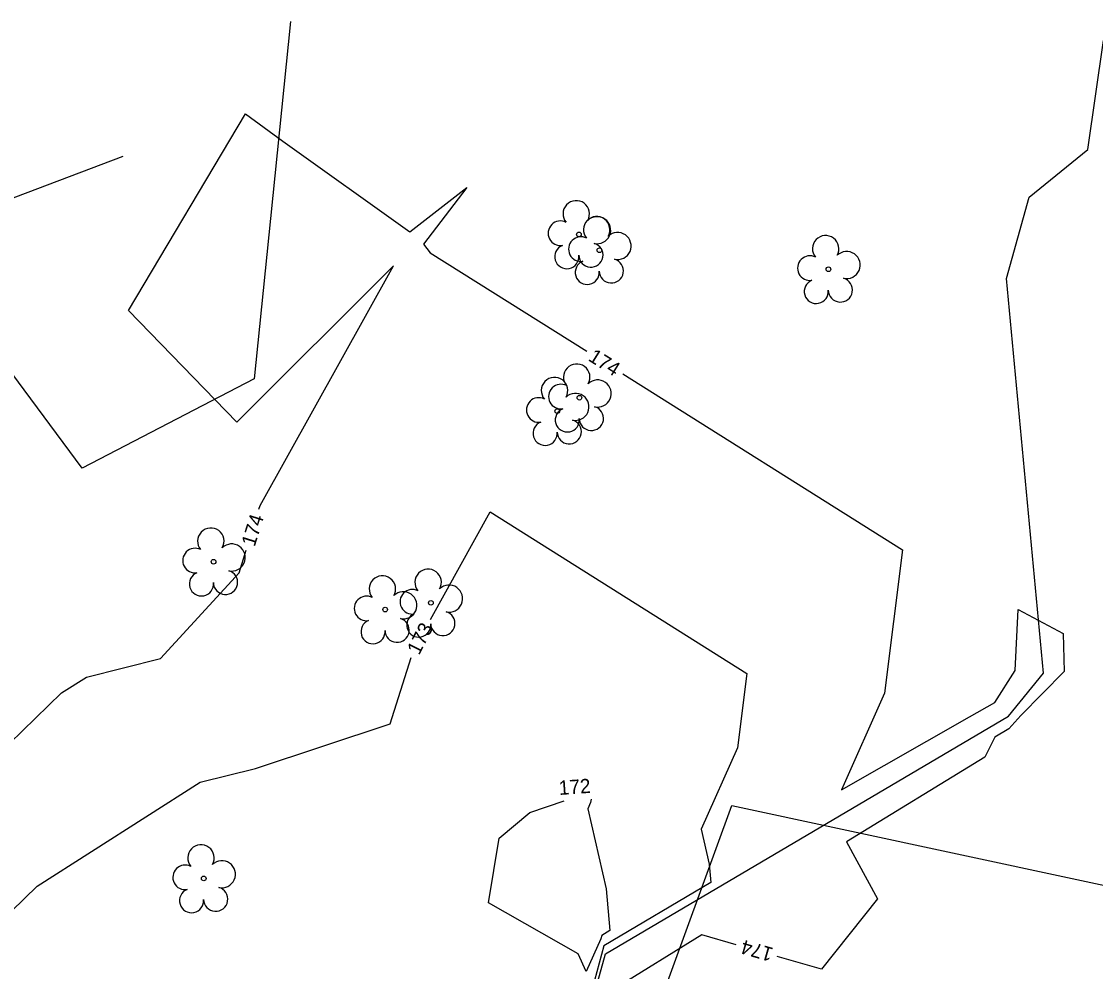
# Model space of a CAD drawing. Extents: x 2086416 to 2115205, y 575507 to 632762.
# Drawn here: x 2112356.1 to 2112506.7, y 581838.5 to 581971.8 of the extents above; entities that cross this region are included whole.
import ezdxf

# ---------------------------------------------------------------- set-up
doc = ezdxf.new("R2010")
doc.units = 0
for name, color, linetype in [('DTM Contours Minor', 7, 'Continuous'), ('DTM Contours Minor Text', 7, 'Continuous'), ('Exist Hydro Stream or Body of Water', 7, 'Continuous'), ('Exist Vegetation Tree CELL', 7, 'Continuous'), ('Exist Vegetation Woods Line', 7, 'Continuous')]:
    doc.layers.add(name, color=color, linetype=linetype)

# ---------------------------------------------------------------- blocks, each defined once
blk = doc.blocks.new('EXIST VEGETATION TREE')
at = {"layer": 'Exist Vegetation Tree CELL'}
blk.add_line((0, 0), (0, 0), dxfattribs=at)
blk.add_circle((0, 0), 0.00652, dxfattribs=at)
for centre, radius, start, end in [((-0.0077, 0.0575), 0.0371, 330.1651, 219.7134), ((-0.0521, 0.0031), 0.0345, 62.6636, 279.3457), ((0.051, 0.0118), 0.038, 257.1011, 134.1999), ((0.0335, -0.058), 0.034, 181.2822, 74.56), ((-0.0341, -0.0624), 0.0338, 111.5671, 6.231)]:
    blk.add_arc(centre, radius, start, end, dxfattribs=at)

msp = doc.modelspace()

# ---------------------------------------------------------------- linework, layer by layer
at = {"layer": 'DTM Contours Minor'}
for points in [[(2112389.4, 581903.35), (2112389.57, 581903.86), (2112408.27, 581937.5), (2112386.3, 581915.55), (2112371.1, 581931.24), (2112387.5, 581958.79), (2112392.75, 581954.99), (2112410.55, 581942.25), (2112418.57, 581948.48), (2112412.46, 581940.54), (2112413.43, 581939.32), (2112435.37, 581925.52)], [(2112315.08, 581919.53), (2112313.29, 581930.07), (2112313.19, 581931.24), (2112370.35, 581952.85)], [(2112440.45, 581922.33), (2112479.65, 581897.67), (2112477.15, 581877.58), (2112471.1, 581864.01), (2112489.03, 581874.23), (2112492.6, 581876.27), (2112495.44, 581880.72), (2112495.89, 581889.28), (2112502.17, 581885.91), (2112502.32, 581880.59), (2112496.23, 581874.43), (2112494.55, 581872.58), (2112492.59, 581871.4), (2112491.2, 581868.61), (2112471.79, 581856.7), (2112476.16, 581848.74), (2112468.31, 581838.85), (2112462.08, 581840.63)], [(2112413.46, 581887.91), (2112421.83, 581902.97), (2112457.83, 581880.33), (2112456.53, 581869.89), (2112451.44, 581858.48), (2112452.56, 581853.57), (2112452.79, 581851), (2112437.76, 581842.11), (2112436.14, 581836.06), (2112433.26, 581829.68), (2112433.26, 581827.76), (2112434.19, 581823.75), (2112429.9, 581818.37), (2112413.96, 581808.4), (2112399.59, 581805.8), (2112390.32, 581804.96), (2112388.42, 581810.88), (2112378.02, 581812.27), (2112371.53, 581811.37)], [(2112254.07, 581816.2), (2112270.16, 581818.14), (2112276.22, 581818.7), (2112299.96, 581821.57), (2112307.56, 581822.62), (2112329.58, 581826.32), (2112343.62, 581828.68), (2112345.41, 581828.91), (2112345.86, 581828.8), (2112351.13, 581828.16), (2112351.3, 581828.82), (2112352.42, 581829.9), (2112349.84, 581834.07), (2112347.16, 581839.69), (2112345.41, 581840.74), (2112341.86, 581842.42), (2112341.8, 581842.53), (2112336.33, 581854.64), (2112337.93, 581854.53), (2112361.72, 581877.6), (2112365.19, 581879.81), (2112375.59, 581882.41), (2112386.63, 581894.46), (2112387.61, 581897.62)], [(2112354.67, 581847.01), (2112358.28, 581850.51), (2112381.14, 581865.06), (2112388.93, 581867.01), (2112407.82, 581873.27), (2112410.73, 581882.58)], [(2112434.16, 581841.02), (2112421.57, 581848.14), (2112423.11, 581857.22), (2112427.37, 581860.84), (2112432.21, 581862.45)], [(2112435.97, 581862.71), (2112435.91, 581862.21), (2112435.53, 581861.35), (2112438.1, 581850.12), (2112438.61, 581844.26), (2112437.47, 581843.58), (2112437.35, 581843.12), (2112435.28, 581838.55), (2112434.16, 581841.02)], [(2112456.32, 581842.29), (2112451.53, 581843.66), (2112439.13, 581836.01)]]:
    msp.add_lwpolyline(points, dxfattribs=at)
at = {"layer": 'Exist Hydro Stream or Body of Water'}
for points in [[(2112499.44, 581880.39), (2112494.24, 581935.71), (2112497.4, 581947.12), (2112505.67, 581953.82), (2112507.86, 581969.07)], [(2112100.33, 581748.53), (2112103.12, 581756.42), (2112105.73, 581760.69), (2112110.23, 581763.66), (2112118.22, 581768.14), (2112152.91, 581774.53), (2112200.71, 581786.3), (2112247.28, 581789.73), (2112301.11, 581801.74), (2112342.55, 581803.72), (2112346.94, 581801.46), (2112350.79, 581799.08), (2112399.71, 581802.75), (2112440.35, 581810.49), (2112440.68, 581811.97), (2112437.89, 581820.2), (2112440.3, 581822.2), (2112435.86, 581828.25), (2112435.37, 581831.56), (2112437.98, 581841.01), (2112494.54, 581874.35), (2112499.44, 581880.39)]]:
    msp.add_lwpolyline(points, dxfattribs=at)
at = {"layer": 'Exist Vegetation Woods Line'}
for points in [[(2112393.84, 581971.76), (2112391.03, 581944.12), (2112388.74, 581921.66), (2112364.61, 581909.13), (2112347.49, 581932.18), (2112342.54, 581966.24)], [(2112455.71, 581861.8), (2112519.59, 581848.11), (2112580.68, 581853.15), (2112624.48, 581854.23), (2112655.73, 581864.5)], [(2112301.36, 581782.95), (2112202.06, 581766.89), (2112123.13, 581753.42), (2112119.41, 581763.53), (2112200.97, 581777.22), (2112301.44, 581791.88), (2112399.2, 581802.76), (2112436.7, 581809.61), (2112455.71, 581861.8)]]:
    msp.add_lwpolyline(points, dxfattribs=at)

# ---------------------------------------------------------------- block references
at = {"layer": 'Exist Vegetation Tree CELL', "xscale": 50, "yscale": 50}
for p in [(2112434.28, 581941.9), (2112437.15, 581939.68), (2112469.27, 581937.01), (2112434.35, 581919), (2112431.24, 581917.12), (2112383.03, 581896), (2112413.51, 581890.23), (2112407.1, 581889.29), (2112381.65, 581851.58)]:
    msp.add_blockref('EXIST VEGETATION TREE', p, dxfattribs=at)

# ---------------------------------------------------------------- texts
at = {"layer": 'DTM Contours Minor Text'}
for s, rotation, p in [('174', 327.8308, (2112435.45, 581924.29)), ('174', 72.6436, (2112388.79, 581898.01)), ('173', 62.8914, (2112411.85, 581882.8)), ('172', 3.9754, (2112431.51, 581863.28)), ('174', 163.9879, (2112461.66, 581841.79))]:
    msp.add_text(s, height=2, rotation=rotation, dxfattribs=at).set_placement(p)

doc.saveas('drawing.dxf')
